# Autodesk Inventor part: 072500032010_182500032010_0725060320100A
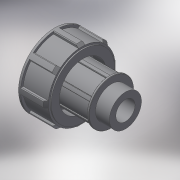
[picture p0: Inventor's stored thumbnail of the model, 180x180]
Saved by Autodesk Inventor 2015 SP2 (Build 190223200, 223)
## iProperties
Created: 2017-04
Part Number: 072500032010_182500032010_0725060320100A
Material: Generic
Description: PLASSON THREADED ADAPTOR 32-1"
Document SubType Name: Modeling
Designer: KIM
Density: 1 g/cm^3
Appearance: Default
Author: KIM
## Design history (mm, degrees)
derived "07250.ipt"
feature "Solid1::07250.ipt"
tag "TaggingFeature1"
body "Solid1"
other parameters: "d1" = 33.249, "d2" = 87, "d6" = 64, "d7" = 59.52, "d8" = 51.2, "d9" = 32, "d10" = 39.8988, "d12" = 19.9494, "d13" = 26.5992, "d14" = 23, "d15" = 48, "d16" = 2.61, "d17" = 34.8, "d19" = 24, "d24" = 6.6498, "d25" = 3.3249, "d27" = 0, "d28" = 2.65992, "d31" = 0.66498, "d35" = 360 deg, "d41" = 29.337, "d56" = 35.2, "d57" = 3.2, "d58" = 1.6, "d60" = 0, "d61" = 0.33249, "d64" = 0.33249, "d68" = 360 deg, "d_" = 32, "R_" = 33.249, "E_" = 64, "H_" = 87, "d55" = 32
